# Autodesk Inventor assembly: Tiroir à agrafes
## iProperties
Author: Flavien MARTY
Shininess: 21.0
PropertySet Name: _Private Model Information
Created: 2001-10
Part Number: Tiroir à agrafes
Document SubType Name: Assemblage
Designer: Flavien MARTY
Control State: 0
Master: False
Checked Out: False
PropertySet Name: Design Tracking Control
Density: 0.0
Volumn: 0.0
Area: 0.0
PropertySet Name: Model Information
